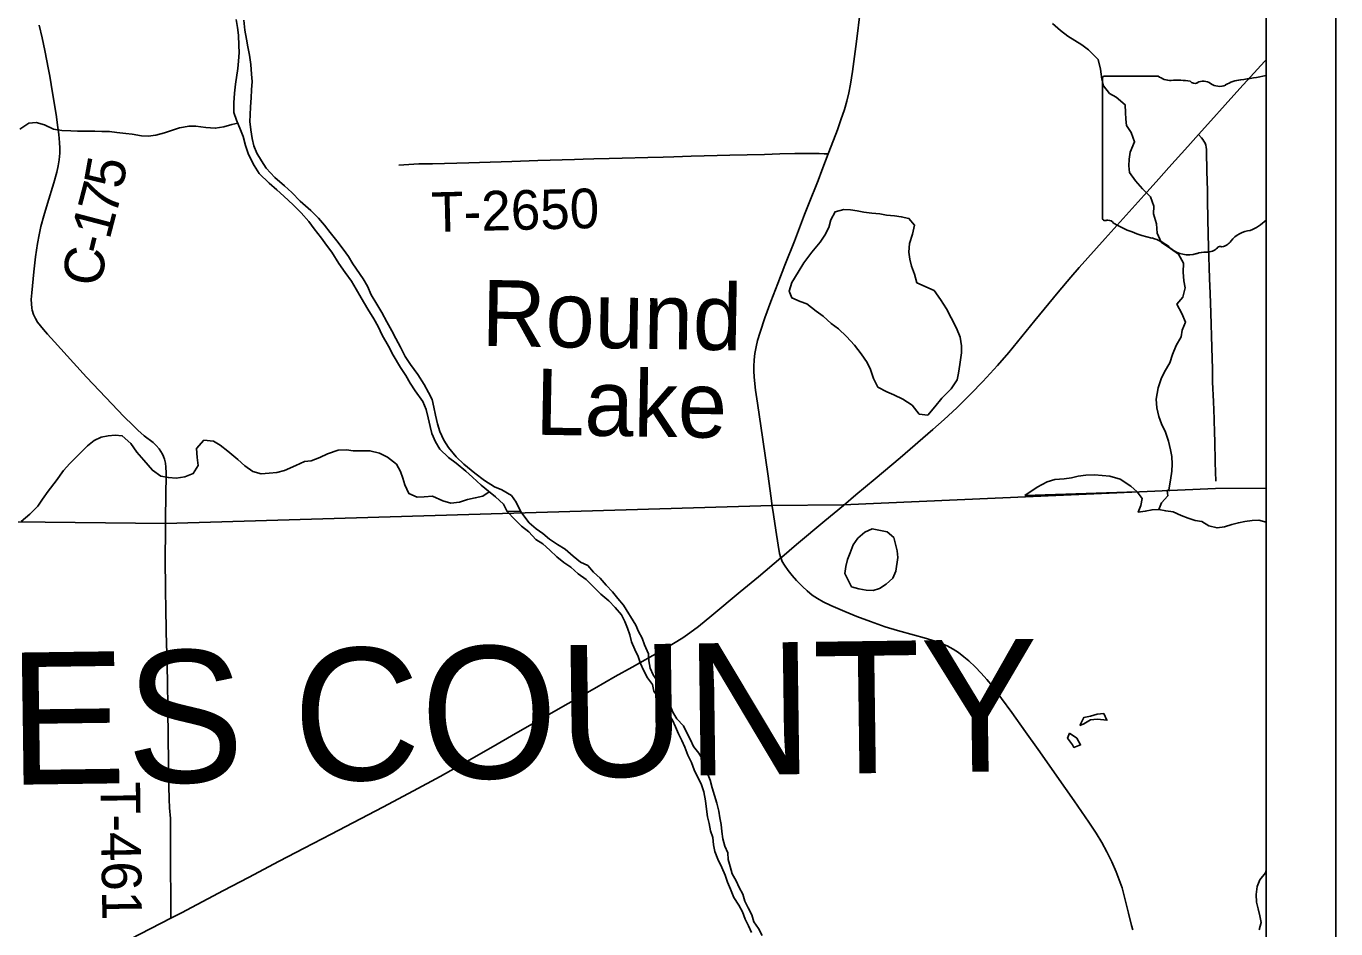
# Model space of a CAD drawing. Extents: x 0 to 34, y 0 to 22.
# Drawn here: x 6.882 to 8.76, y 18.172 to 19.466 of the extents above; entities that cross this region are included whole.
import ezdxf

# ---------------------------------------------------------------- set-up
doc = ezdxf.new("R2010")
doc.units = 0
for name, color, linetype in [('GM_X_County_Road', 7, 'Continuous'), ('GM_X_County_Road_Text', 7, 'Continuous'), ('GM_X_Interchange_Ramps', 7, 'Continuous'), ('GM_X_Major_River_Text', 7, 'Continuous'), ('GM_X_Minor_River_Text', 7, 'Continuous'), ('GM_X_Rail_Line', 7, 'Continuous'), ('GM_X_Section_Text', 7, 'Continuous'), ('GM_X_State_Route', 7, 'Continuous'), ('GM_X_State_Shield', 7, 'Continuous'), ('GM_X_Township_Road', 7, 'Continuous'), ('GM_X_Township_Road_Text', 7, 'Continuous'), ('GM_X_Township_Text', 7, 'Continuous'), ('GM_X_Unincorporated_Location', 7, 'Continuous'), ('SH_Data', 7, 'Continuous')]:
    doc.layers.add(name, color=color, linetype=linetype)

msp = doc.modelspace()

# ---------------------------------------------------------------- linework, layer by layer
at = {"layer": 'GM_X_County_Road'}
for points in [[(7.9521, 18.7781), (7.9501, 18.7925), (7.9465, 18.8211), (7.9387, 18.8733), (7.9308, 18.9256), (7.9282, 18.9441), (7.9263, 18.9626), (7.9257, 18.972), (7.9256, 18.9783), (7.9261, 18.9876), (7.9273, 18.9969), (7.929, 19.0062), (7.9311, 19.0153), (7.9346, 19.0272), (7.9414, 19.0479), (7.9501, 19.0712), (7.9601, 19.0973), (7.9704, 19.1233), (7.9839, 19.158), (7.9984, 19.1958), (8.004, 19.2102), (8.0178, 19.2449), (8.0234, 19.2593), (8.0325, 19.2829), (8.0335, 19.2854), (8.0455, 19.3173), (8.0507, 19.3319), (8.0556, 19.3467), (8.059, 19.3586), (8.062, 19.3706), (8.0644, 19.3827), (8.0672, 19.4011), (8.0729, 19.4442), (8.0782, 19.4873)], [(8.0541, 18.779), (8.072, 18.794), (8.0997, 18.8173), (8.1355, 18.847), (8.1826, 18.8876), (8.1988, 18.9021), (8.2169, 18.9191), (8.2369, 18.9387), (8.2541, 18.9566), (8.275, 18.9796), (8.2913, 18.9983), (8.3285, 19.0441), (8.362, 19.0849), (8.3801, 19.1061), (8.3924, 19.1201), (8.4296, 19.1618), (8.4899, 19.2286), (8.5064, 19.2472), (8.521, 19.2633), (8.5479, 19.2933), (8.5635, 19.3107), (8.5811, 19.3302), (8.6018, 19.3533), (8.6224, 19.3765), (8.658, 19.4154), (8.6602, 19.4177)], [(7.9644, 18.7039), (7.9627, 18.71), (7.9605, 18.7222), (7.9571, 18.7437), (7.9539, 18.7661), (7.9521, 18.7781)], [(7.9644, 18.7039), (7.9657, 18.705), (7.9871, 18.723), (8.0276, 18.757), (8.0541, 18.779)], [(7.0028, 18.1422), (7.0896, 18.1872), (7.1048, 18.1951), (7.1653, 18.2269), (7.2011, 18.2457), (7.2451, 18.2688), (7.2809, 18.2875), (7.3195, 18.3076), (7.3939, 18.3464), (7.4378, 18.3697), (7.476, 18.3904), (7.514, 18.4117), (7.5517, 18.4334), (7.5841, 18.4519), (7.6973, 18.5165), (7.7269, 18.5335), (7.7513, 18.5472), (7.7919, 18.5702), (7.8107, 18.581), (7.8239, 18.5892), (7.8341, 18.5962), (7.8465, 18.6055), (7.8657, 18.6212), (7.9063, 18.6551), (7.9326, 18.6768), (7.9644, 18.7039)], [(8.469, 18.1705), (8.4671, 18.1765), (8.4628, 18.1944), (8.4577, 18.2153), (8.4537, 18.2305), (8.4497, 18.2422), (8.4452, 18.2538), (8.4389, 18.2681), (8.432, 18.2821), (8.4245, 18.2957), (8.4164, 18.309), (8.4062, 18.3247), (8.385, 18.3553), (8.3601, 18.391), (8.3458, 18.4113), (8.3334, 18.4292), (8.3155, 18.4545), (8.2956, 18.4822), (8.281, 18.5023), (8.2679, 18.5197), (8.26, 18.5294), (8.2517, 18.5387), (8.243, 18.5475), (8.2339, 18.5561), (8.2268, 18.5621), (8.2192, 18.5679), (8.2115, 18.573), (8.2031, 18.5775), (8.1943, 18.5812), (8.1859, 18.5842), (8.17, 18.5889), (8.1561, 18.5928), (8.1315, 18.5998), (8.1142, 18.605), (8.0932, 18.6125), (8.0734, 18.6199), (8.0561, 18.6269), (8.0362, 18.6354), (8.025, 18.6407), (8.017, 18.6453), (8.0094, 18.6505), (8.0022, 18.6563), (7.9953, 18.6625), (7.9867, 18.6714), (7.9806, 18.6784), (7.9749, 18.6857), (7.9696, 18.6933), (7.9665, 18.6985), (7.9652, 18.7013), (7.9644, 18.7039)]]:
    msp.add_lwpolyline(points, dxfattribs=at)
at = {"layer": 'GM_X_County_Road_Text'}
for points in [[(8.5183, 18.8002), (8.5206, 18.8014), (8.5232, 18.8151), (8.5251, 18.828), (8.5254, 18.8383), (8.525, 18.8489), (8.5234, 18.8587), (8.5204, 18.8709), (8.5158, 18.8838), (8.5104, 18.8959), (8.5066, 18.9065), (8.5035, 18.919), (8.5027, 18.9311), (8.5056, 18.9475), (8.5098, 18.9604), (8.5146, 18.9703), (8.5222, 18.9832), (8.5259, 18.9954), (8.5315, 19.0083), (8.5383, 19.0205), (8.5398, 19.03), (8.5447, 19.0417), (8.5393, 19.0542), (8.5324, 19.0675), (8.5411, 19.0774), (8.5441, 19.0907), (8.5425, 19.1009), (8.5413, 19.1135), (8.5417, 19.1264), (8.5348, 19.1392), (8.5234, 19.1472), (8.5097, 19.1566), (8.504, 19.1691), (8.5031, 19.1828), (8.4989, 19.1968), (8.4992, 19.2082), (8.4943, 19.2214), (8.4832, 19.2328), (8.4729, 19.2441), (8.4646, 19.2562), (8.4634, 19.2657), (8.4637, 19.2756), (8.4652, 19.2855), (8.4716, 19.3003), (8.4666, 19.3135), (8.4601, 19.3234), (8.4593, 19.3329), (8.4589, 19.3424), (8.4581, 19.3534), (8.4452, 19.3643), (8.4357, 19.3696), (8.4273, 19.3806), (8.4246, 19.39), (8.423, 19.4045), (8.4196, 19.4181), (8.4058, 19.4321), (8.396, 19.4393), (8.3861, 19.4453), (8.3762, 19.4517), (8.3656, 19.46), (8.3538, 19.4698)], [(7.1858, 19.3272), (7.1773, 19.325), (7.1659, 19.3219), (7.1534, 19.3196), (7.1398, 19.3207), (7.1254, 19.3229), (7.1159, 19.3229), (7.1023, 19.3202), (7.0905, 19.3163), (7.0807, 19.3129), (7.0682, 19.3098), (7.0572, 19.3082), (7.0477, 19.3086), (7.0345, 19.3112), (7.025, 19.3123), (7.0125, 19.3137), (7.0019, 19.3148), (6.9909, 19.3148), (6.9806, 19.3155), (6.956, 19.3154), (6.9465, 19.3158), (6.9333, 19.3165), (6.9215, 19.3183), (6.9086, 19.3244), (6.8965, 19.3277), (6.8862, 19.3269), (6.8734, 19.3182)], [(7.546, 18.7986), (7.5373, 18.792), (7.5263, 18.7897), (7.5149, 18.7874), (7.5036, 18.7835), (7.4914, 18.782), (7.4797, 18.7857), (7.4649, 18.7921), (7.4528, 18.7913), (7.4429, 18.7909), (7.4308, 18.7962), (7.4254, 18.8087), (7.4223, 18.8182), (7.4189, 18.8276), (7.4131, 18.8379), (7.4006, 18.8481), (7.3888, 18.8541), (7.3752, 18.8574), (7.3513, 18.8574), (7.3418, 18.8585), (7.3297, 18.8584), (7.3145, 18.853), (7.3036, 18.8477), (7.2911, 18.8427), (7.2812, 18.8419), (7.2688, 18.8362), (7.2525, 18.8289), (7.2415, 18.8262), (7.2309, 18.825), (7.2192, 18.8242), (7.2074, 18.8276), (7.1956, 18.8355), (7.1857, 18.845), (7.1713, 18.8567), (7.1606, 18.8654), (7.1508, 18.871), (7.1371, 18.8725), (7.1265, 18.8607), (7.1277, 18.8478), (7.1289, 18.836), (7.1218, 18.8246), (7.1097, 18.82), (7.0972, 18.8181), (7.0862, 18.8188), (7.0756, 18.821), (7.0634, 18.8293), (7.0508, 18.8437), (7.0409, 18.8554), (7.0325, 18.8679), (7.02, 18.8789), (7.0101, 18.8796), (6.9999, 18.8788), (6.99, 18.8769), (6.9798, 18.8719), (6.97, 18.8646), (6.9568, 18.8509), (6.9451, 18.8391), (6.9357, 18.8292), (6.9255, 18.814), (6.9138, 18.7995), (6.9059, 18.7881), (6.8988, 18.7778), (6.8874, 18.7664), (6.875, 18.7557)], [(8.5066, 18.773), (8.5105, 18.7828), (8.5193, 18.7926), (8.5183, 18.8002)], [(8.6505, 18.1706), (8.6533, 18.1808), (8.6515, 18.1907), (8.6489, 18.2006), (8.6467, 18.2101), (8.646, 18.2211), (8.6476, 18.2324), (8.6515, 18.2423), (8.6592, 18.2524), (8.6602, 18.2554)]]:
    msp.add_lwpolyline(points, dxfattribs=at)
at = {"layer": 'GM_X_Interchange_Ramps'}
for points in [[(8.5863, 18.8822), (8.5857, 18.9032), (8.5847, 18.928), (8.5836, 18.9558), (8.5832, 18.9744), (8.5825, 19.0054), (8.581, 19.0549), (8.58, 19.0828), (8.5792, 19.1045), (8.5786, 19.1199), (8.5783, 19.1354), (8.5774, 19.1662), (8.5766, 19.1906), (8.5763, 19.215), (8.5761, 19.2305), (8.5755, 19.2584), (8.5749, 19.2863), (8.5748, 19.2894), (8.5744, 19.2924), (8.5739, 19.2954), (8.5728, 19.2983), (8.5712, 19.301), (8.5694, 19.3035), (8.5675, 19.3059), (8.5635, 19.3107)], [(7.4165, 19.267), (7.4452, 19.2685), (7.4647, 19.2689), (7.5169, 19.2703), (7.5478, 19.2712), (7.5633, 19.2716), (7.5788, 19.272), (7.616, 19.2734), (7.6686, 19.2749), (7.681, 19.2753), (7.6965, 19.2757), (7.7182, 19.2762), (7.7367, 19.2767), (7.7739, 19.2776), (7.7956, 19.2783), (7.8111, 19.2788), (7.8359, 19.2795), (7.873, 19.2808), (7.8915, 19.2813), (7.9411, 19.2822), (7.9628, 19.2829), (7.9845, 19.2834), (8.0062, 19.2837), (8.0154, 19.2834), (8.0192, 19.2833), (8.0264, 19.2831), (8.0325, 19.2829)], [(8.5881, 18.8135), (8.5874, 18.8403), (8.5866, 18.8722), (8.5863, 18.8822)], [(7.0896, 18.1872), (7.0896, 18.1945), (7.0895, 18.2181), (7.0892, 18.2586), (7.089, 18.2803), (7.089, 18.3145), (7.089, 18.33), (7.088, 18.3455), (7.0873, 18.3579), (7.087, 18.3765), (7.0868, 18.3889), (7.0864, 18.4105), (7.0862, 18.4228), (7.0859, 18.435), (7.0858, 18.4381), (7.0857, 18.4564), (7.0854, 18.4779), (7.0854, 18.484), (7.0849, 18.5306), (7.0846, 18.543), (7.0838, 18.5709), (7.0836, 18.577), (7.0836, 18.58), (7.0832, 18.5986), (7.0829, 18.6079), (7.0827, 18.6234), (7.0824, 18.6358), (7.0822, 18.6513), (7.0819, 18.6667), (7.0817, 18.6946), (7.0817, 18.7132), (7.0819, 18.7318), (7.0821, 18.7472), (7.0822, 18.7527)]]:
    msp.add_lwpolyline(points, dxfattribs=at)
at = {"layer": 'GM_X_Minor_River_Text'}
msp.add_line((8.3145, 18.7934), (8.4756, 18.7986), dxfattribs=at)
for points in [[(8.1594, 19.098), (8.1559, 19.1105), (8.1517, 19.1218), (8.1494, 19.1321), (8.1482, 19.1419), (8.1489, 19.1545), (8.153, 19.1678), (8.156, 19.1807), (8.148, 19.1905), (8.137, 19.1928), (8.1272, 19.1939), (8.1158, 19.1953), (8.1063, 19.1968), (8.0949, 19.1979), (8.0836, 19.1994), (8.0737, 19.2012), (8.0642, 19.2027), (8.0547, 19.2034), (8.0422, 19.2), (8.0362, 19.1886), (8.0332, 19.1776), (8.0276, 19.1665), (8.0208, 19.1563), (8.0091, 19.1422), (7.9974, 19.1266), (7.9895, 19.1136), (7.9801, 19.0984), (7.9764, 19.0859), (7.9802, 19.0764), (7.992, 19.0715), (8.0015, 19.0678), (8.0152, 19.0576), (8.0251, 19.0504), (8.0365, 19.0398), (8.0471, 19.0319), (8.0585, 19.0213), (8.0703, 19.0088), (8.0798, 18.9963), (8.0882, 18.9838), (8.0928, 18.974), (8.0974, 18.9607), (8.1035, 18.9486), (8.1165, 18.9418), (8.1267, 18.9377), (8.1396, 18.9313), (8.1529, 18.9226), (8.1628, 18.9098), (8.175, 18.9083), (8.1855, 18.9205), (8.1953, 18.9326), (8.2085, 18.946), (8.2172, 18.9589), (8.2191, 18.9684), (8.2213, 18.9809), (8.2235, 18.9976), (8.2234, 19.0079), (8.2215, 19.0204), (8.2165, 19.0333), (8.2085, 19.0481), (8.202, 19.0609), (8.1932, 19.0742), (8.1841, 19.0871)], [(8.1841, 19.0871), (8.1594, 19.098)], [(8.4756, 18.7986), (8.4661, 18.8065), (8.4509, 18.8167), (8.4361, 18.8208), (8.4254, 18.8219), (8.4144, 18.8227), (8.4019, 18.8222), (8.391, 18.8207), (8.3811, 18.8184), (8.3709, 18.8172), (8.3573, 18.816), (8.3463, 18.8129), (8.3319, 18.8053), (8.3145, 18.7934)], [(8.3145, 18.7934), (8.4756, 18.7986)], [(8.4756, 18.7986), (8.4825, 18.7891), (8.4805, 18.7789), (8.477, 18.7691), (8.4869, 18.7705), (8.4967, 18.7727), (8.5066, 18.773), (8.5164, 18.771), (8.527, 18.7698), (8.5387, 18.7647), (8.5486, 18.7608), (8.5584, 18.7573), (8.5682, 18.7557), (8.5784, 18.7499), (8.5901, 18.7468), (8.6004, 18.7482), (8.611, 18.7515), (8.6205, 18.7541), (8.63, 18.7559), (8.6403, 18.7574), (8.6501, 18.758), (8.6602, 18.7551)], [(8.0955, 18.7452), (8.0848, 18.7404), (8.0749, 18.7321), (8.068, 18.7223), (8.0637, 18.711), (8.0602, 18.7012), (8.0575, 18.6913), (8.0563, 18.6815), (8.0608, 18.672), (8.066, 18.6624), (8.0762, 18.6593), (8.0868, 18.6573), (8.0966, 18.6568), (8.1061, 18.6598)], [(8.1061, 18.6598), (8.1157, 18.6662), (8.1252, 18.6748), (8.1291, 18.6846), (8.1323, 18.7043), (8.1312, 18.7138), (8.1287, 18.7233), (8.1265, 18.7328), (8.1167, 18.7412), (8.0955, 18.7452)], [(8.4275, 18.4718), (8.4321, 18.471), (8.4276, 18.4805), (8.4181, 18.4795), (8.4086, 18.4769), (8.3987, 18.4747), (8.3933, 18.4634)], [(8.3933, 18.4634), (8.399, 18.466), (8.4086, 18.4716), (8.418, 18.4723), (8.4275, 18.4718)], [(8.3785, 18.4525), (8.3757, 18.4454), (8.3825, 18.4358)], [(8.3825, 18.4358), (8.3847, 18.432), (8.3942, 18.4357), (8.389, 18.4452), (8.3785, 18.4525)]]:
    msp.add_lwpolyline(points, dxfattribs=at)
at = {"layer": 'GM_X_State_Route'}
msp.add_lwpolyline([(8.6602, 18.8038), (8.6602, 21.1866), (4.0708, 21.1866), (4.0805, 19.8173), (4.0805, 19.8117), (4.0945, 18.7432), (4.5791, 18.7479), (5.5804, 18.7605), (5.5812, 18.7605), (6.0902, 18.7638), (7.082, 18.7532), (7.9519, 18.7787), (8.0539, 18.7796), (8.5878, 18.803)], close=True, dxfattribs=at)
at = {"layer": 'GM_X_State_Shield'}
msp.add_line((7.5911, 18.7708), (7.5722, 18.7704), dxfattribs=at)
for points in [[(7.1835, 19.4757), (7.1854, 19.4643), (7.1866, 19.4529), (7.1874, 19.4381), (7.1875, 19.4283), (7.1868, 19.4161), (7.186, 19.4055), (7.1823, 19.3827), (7.1809, 19.3698), (7.1802, 19.3561), (7.1802, 19.3421), (7.1841, 19.3315), (7.1898, 19.3174), (7.1933, 19.308), (7.1967, 19.2951), (7.2013, 19.2822), (7.209, 19.2663), (7.2162, 19.2546), (7.2307, 19.2409), (7.2417, 19.2315), (7.2516, 19.2224), (7.2649, 19.21), (7.2767, 19.1986), (7.2878, 19.1861), (7.2954, 19.1755), (7.3057, 19.1623), (7.3129, 19.1521), (7.3205, 19.1419), (7.3305, 19.126), (7.3396, 19.1127), (7.3488, 19.1006), (7.3556, 19.0892), (7.3625, 19.0767), (7.3724, 19.0605), (7.3808, 19.0465), (7.3869, 19.0355), (7.3927, 19.023), (7.4018, 19.0074), (7.4087, 18.9942), (7.419, 18.9768), (7.4266, 18.9654), (7.4331, 18.9541), (7.44, 18.9431), (7.451, 18.9279), (7.456, 18.9166), (7.4587, 18.9044), (7.4614, 18.8919), (7.4641, 18.8821), (7.4691, 18.8699), (7.4756, 18.8597), (7.4881, 18.8476), (7.4988, 18.8393), (7.5125, 18.828), (7.5224, 18.8193), (7.5349, 18.808), (7.5452, 18.7993), (7.5551, 18.7913), (7.5669, 18.7807), (7.5722, 18.7704)], [(7.5911, 18.7708), (7.5847, 18.7835), (7.5782, 18.7933), (7.5645, 18.8012), (7.5539, 18.8057), (7.5394, 18.8148), (7.5257, 18.8254), (7.5098, 18.8382), (7.4991, 18.8488), (7.4881, 18.862), (7.4812, 18.8726), (7.4755, 18.8848), (7.472, 18.8958), (7.4693, 18.9083), (7.467, 18.92), (7.4643, 18.9306), (7.4593, 18.9409), (7.4532, 18.9522), (7.4441, 18.9666), (7.4334, 18.981), (7.4258, 18.9924), (7.4189, 19.006), (7.4124, 19.0185), (7.4067, 19.0291), (7.3994, 19.042), (7.3921, 19.0556), (7.3853, 19.0677), (7.3769, 19.081), (7.3719, 19.0935), (7.3654, 19.1037), (7.3509, 19.1253), (7.3444, 19.1359), (7.3368, 19.1465), (7.3277, 19.1582), (7.3181, 19.1703), (7.3101, 19.1809), (7.3014, 19.1907), (7.2904, 19.2017), (7.2751, 19.2153), (7.2633, 19.2274), (7.2527, 19.2369), (7.239, 19.2489), (7.2264, 19.2626), (7.2196, 19.2732), (7.2131, 19.2838), (7.2089, 19.2944), (7.2065, 19.305), (7.2042, 19.3175), (7.203, 19.3296), (7.2034, 19.3391), (7.2041, 19.3505), (7.2048, 19.3634), (7.2055, 19.3748), (7.2062, 19.3866), (7.2054, 19.3972), (7.2046, 19.4112), (7.2023, 19.4245), (7.2003, 19.4366), (7.198, 19.4473), (7.196, 19.4602), (7.1945, 19.4746)], [(7.5722, 18.7704), (7.5911, 18.7708)], [(7.5722, 18.7704), (7.5828, 18.7586), (7.5925, 18.7494), (7.6031, 18.7409), (7.6132, 18.7302), (7.623, 18.7241), (7.6332, 18.7149), (7.6433, 18.7053), (7.6535, 18.6969), (7.6633, 18.6903), (7.6738, 18.6811), (7.6851, 18.6727), (7.6953, 18.6627), (7.7062, 18.6517), (7.7179, 18.6421), (7.7269, 18.6325), (7.7359, 18.6222), (7.7407, 18.6127), (7.7445, 18.6031), (7.7478, 18.5933), (7.7504, 18.5834), (7.7552, 18.5723), (7.7597, 18.5624), (7.763, 18.5525), (7.7675, 18.5426), (7.7734, 18.532), (7.7802, 18.5224), (7.7824, 18.5125), (7.7902, 18.5022), (7.7973, 18.4916), (7.8022, 18.4816), (7.8089, 18.4713), (7.8134, 18.4615), (7.8175, 18.4516), (7.8223, 18.442), (7.8268, 18.4325), (7.8309, 18.4207), (7.8365, 18.4104), (7.8402, 18.3998), (7.845, 18.3899), (7.8502, 18.3796), (7.8539, 18.3682), (7.8565, 18.3553), (7.8579, 18.3435), (7.8593, 18.3325), (7.8619, 18.323), (7.8637, 18.3123), (7.8667, 18.3028), (7.8677, 18.2926), (7.8699, 18.2827), (7.874, 18.272), (7.8796, 18.2599), (7.8844, 18.2488), (7.8881, 18.2389), (7.8922, 18.229), (7.897, 18.2169), (7.9041, 18.2058), (7.9094, 18.1963), (7.9134, 18.186), (7.9179, 18.1761)], [(7.596, 18.7639), (7.5911, 18.7708)], [(7.7566, 18.6071), (7.739, 18.6358), (7.7308, 18.6454), (7.7229, 18.6549), (7.7139, 18.6645), (7.7056, 18.6748), (7.6958, 18.6832), (7.6876, 18.6928), (7.677, 18.6978), (7.6665, 18.7062), (7.6552, 18.7162), (7.6442, 18.7227), (7.6329, 18.7304), (7.6232, 18.7385), (7.6134, 18.7454), (7.6036, 18.7542), (7.596, 18.7639)], [(7.9375, 18.1626), (7.9323, 18.1722), (7.9259, 18.1821), (7.923, 18.192), (7.9178, 18.2019), (7.9129, 18.2118), (7.91, 18.2217), (7.9047, 18.2312), (7.9003, 18.2407), (7.8947, 18.2506), (7.8917, 18.2613), (7.8888, 18.2712), (7.8885, 18.281), (7.884, 18.2905), (7.8814, 18.3008), (7.88, 18.3114), (7.8789, 18.3213), (7.8768, 18.3312), (7.8753, 18.3407), (7.8728, 18.3521), (7.8661, 18.3741), (7.8632, 18.3852), (7.8595, 18.3947), (7.8569, 18.4046), (7.8524, 18.4141), (7.8468, 18.424), (7.8393, 18.4335), (7.8349, 18.4431), (7.8296, 18.453), (7.8248, 18.4632), (7.8154, 18.4728), (7.8094, 18.4827), (7.805, 18.4945), (7.7986, 18.5063), (7.7934, 18.5166), (7.7874, 18.5265), (7.7814, 18.5361), (7.7773, 18.5456), (7.7751, 18.5562), (7.7745, 18.5661), (7.7689, 18.579), (7.7656, 18.5885), (7.7603, 18.5981), (7.7566, 18.6071)], [(7.9179, 18.1761), (7.9224, 18.1666)]]:
    msp.add_lwpolyline(points, dxfattribs=at)
at = {"layer": 'GM_X_Township_Road'}
msp.add_lwpolyline([(7.0822, 18.7527), (7.0825, 18.8008), (7.083, 18.8156), (7.0828, 18.8256), (7.0826, 18.8339), (7.0821, 18.8396), (7.0805, 18.8453), (7.0792, 18.8489), (7.0776, 18.8526), (7.0754, 18.8562), (7.0728, 18.8601), (7.0687, 18.8648), (7.0642, 18.869), (7.0517, 18.8787), (7.0425, 18.887), (7.0356, 18.8934), (7.0224, 18.9066), (6.9967, 18.9336), (6.969, 18.963), (6.95, 18.9835), (6.9229, 19.0133), (6.9128, 19.0244), (6.907, 19.0312), (6.9026, 19.0364), (6.8986, 19.0417), (6.8955, 19.047), (6.8929, 19.0527), (6.8911, 19.0587), (6.8905, 19.0618), (6.8898, 19.068), (6.8896, 19.0742), (6.8905, 19.0836), (6.8934, 19.1137), (6.8958, 19.1353), (6.8986, 19.1546), (6.9008, 19.1668), (6.9035, 19.1788), (6.9075, 19.1939), (6.9127, 19.2118), (6.9219, 19.2412), (6.9261, 19.2566), (6.9281, 19.2656), (6.9295, 19.2744), (6.9304, 19.2838), (6.9305, 19.2909), (6.9303, 19.2994), (6.929, 19.3106), (6.9277, 19.3209), (6.9251, 19.3392), (6.9201, 19.3703), (6.916, 19.3943), (6.9143, 19.4041), (6.909, 19.431), (6.9052, 19.4492), (6.9009, 19.4673)], dxfattribs=at)
at = {"layer": 'GM_X_Unincorporated_Location'}
for p, q in [((8.4256, 19.3911), (8.4256, 19.191)), ((8.5054, 19.3945), (8.4282, 19.3945)), ((8.6602, 19.188), (8.6602, 19.3954))]:
    msp.add_line(p, q, dxfattribs=at)
for centre, radius, start, end in [((8.4286, 19.3915), 0.00305, 98.978, 188.5967), ((8.5238, 19.4178), 0.0296, 231.6404, 271.1117), ((8.5336, 19.2822), 0.1064, 80.4867, 94.9883), ((8.5578, 19.3925), 0.00855, 219.7921, 297.1024), ((8.5703, 19.3694), 0.0178, 54.4667, 119.1411), ((8.5933, 19.4011), 0.0214, 233.8562, 294.8282), ((8.631, 19.3334), 0.0563, 97.3462, 120.7689), ((8.5954, 19.6674), 0.2796, 275.8445, 283.4188), ((8.4287, 19.1905), 0.00308, 171.4911, 258.3065), ((8.4291, 19.211), 0.0235, 267.339, 280.6039), ((8.4339, 19.1794), 0.00848, 29.7484, 93.2717), ((8.541, 19.3592), 0.2019, 240.4129, 257.1985), ((8.611, 19.2377), 0.0699, 292.3089, 314.7368), ((8.4808, 19.1011), 0.0632, 47.1842, 75.836), ((8.592, 19.1716), 0.0226, 282.8732, 323.2771), ((8.6405, 19.1348), 0.0383, 94.4031, 142.5768), ((8.5491, 19.1784), 0.0401, 230.7004, 286.2918), ((8.5723, 19.1092), 0.0329, 85.6951, 111.21), ((8.5752, 19.1634), 0.0214, 268.777, 315.5493), ((8.5945, 19.1441), 0.00601, 65.7517, 132.6484)]:
    msp.add_arc(centre, radius, start, end, dxfattribs=at)
at = {"layer": 'SH_Data'}
for points in [[(1.7602, 21.2866), (8.7602, 21.2866), (8.7602, 14.2866), (1.7602, 14.2866)], [(1.8602, 21.1866), (8.6602, 21.1866), (8.6602, 14.3866), (1.8602, 14.3866)]]:
    msp.add_lwpolyline(points, close=True, dxfattribs=at)

# ---------------------------------------------------------------- texts
at = {"layer": 'GM_X_Major_River_Text'}
for s in ['s', 'r']:
    msp.add_text(s, height=0.000189, dxfattribs=at).set_placement((8.5545, 19.2777))
msp.add_text('3', height=0.000189, rotation=0, dxfattribs=at).set_placement((8.5259, 19.2639))
at = {"layer": 'GM_X_Rail_Line'}
msp.add_text('HOLMES COUNTY', height=0.189394, rotation=0.7747, dxfattribs=at).set_placement((6.1262, 18.3685))
at = {"layer": 'GM_X_Section_Text'}
for s, rotation, p in [('5', 79.6224, (7.0204, 19.231)), ('7', 75.4023, (7.0106, 19.1927)), ('1', 75.3264, (7.0017, 19.1587)), ('-', 76.2061, (6.9962, 19.1363)), ('C', 82.3391, (6.9903, 19.0916))]:
    msp.add_text(s, height=0.0568, rotation=rotation, dxfattribs=at).set_placement(p)
at = {"layer": 'GM_X_Township_Road_Text'}
for s, p in [('Round', (7.5349, 19.0077)), ('Lake', (7.6119, 18.8804))]:
    msp.add_text(s, height=0.09471, rotation=358.9928, dxfattribs=at).set_placement(p)
at = {"layer": 'GM_X_Township_Text'}
for s, rotation, p in [('T-2650', 1.4034, (7.4639, 19.1709)), ('T-461', 270.7998, (6.9888, 18.3823))]:
    msp.add_text(s, height=0.05682, rotation=rotation, dxfattribs=at).set_placement(p)

doc.saveas('drawing.dxf')
